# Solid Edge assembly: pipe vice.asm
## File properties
Author: Deepak Maini
Template: normal.asm
Last saved by: CADCIM
Revision: 10
Application: Solid Edge
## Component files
base.par
Screw.par
moveable jaw.par
handle.par
handle screw.par
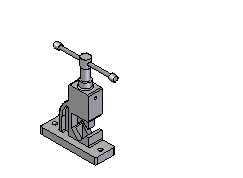
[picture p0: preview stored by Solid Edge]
